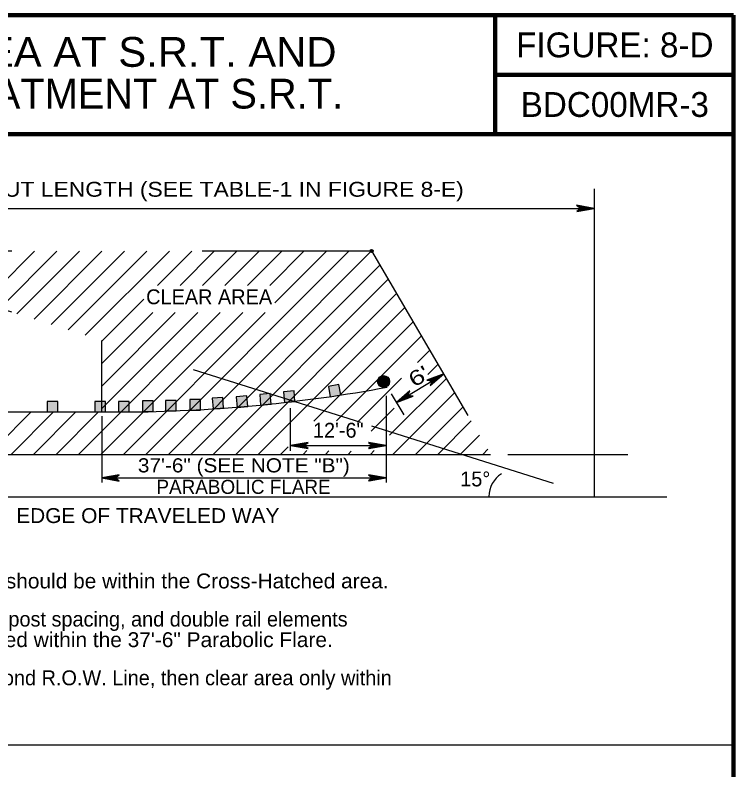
# Model space of a CAD drawing. Extents: x 11.149 to 11.823, y 1.038 to 1.922.
# Drawn here: x 11.4007 to 11.7779, y 1.4804 to 1.8762 of the extents above; entities that cross this region are included whole.
import ezdxf
from ezdxf.enums import TextEntityAlignment as Align

# ---------------------------------------------------------------- set-up
doc = ezdxf.new("R2010")
doc.units = 0
doc.header["$LTSCALE"] = 0.0031
doc.header["$PDMODE"] = 32
doc.header["$PDSIZE"] = 0.00155
doc.linetypes.add('LONG_DASHED', pattern=[7.5, 6, -1.5])
for name, color, linetype, lineweight in [('1', 7, 'Continuous', 90), ('21', 7, 'Continuous', 25), ('24', 7, 'Continuous', 25), ('40', 7, 'Continuous', 25), ('5', 7, 'LONG_DASHED', 25), ('60', 7, 'Continuous', 25)]:
    doc.layers.add(name, color=color, linetype=linetype, lineweight=lineweight)

msp = doc.modelspace()

# ---------------------------------------------------------------- hatches: boundary and pattern name
at = {"layer": '60'}
for points in [[(11.565075, 1.681492), (11.566058, 1.676025), (11.571525, 1.677008), (11.570542, 1.682475)], [(11.541542, 1.678608), (11.542017, 1.673075), (11.54755, 1.673558), (11.547075, 1.679092)], [(11.492433, 1.674642), (11.492433, 1.669092), (11.497983, 1.669092), (11.497983, 1.674642)], [(11.504067, 1.67525), (11.504542, 1.669708), (11.510083, 1.670192), (11.5096, 1.675725)], [(11.51675, 1.676042), (11.517233, 1.670508), (11.522767, 1.670992), (11.522292, 1.676525)], [(11.529042, 1.677242), (11.529517, 1.671708), (11.53505, 1.672183), (11.534575, 1.677725)], [(11.417575, 1.673642), (11.417575, 1.668092), (11.423125, 1.668092), (11.423125, 1.673642)], [(11.442575, 1.673642), (11.442575, 1.668092), (11.448125, 1.668092), (11.448125, 1.673642)], [(11.454892, 1.673658), (11.454892, 1.6681), (11.460442, 1.6681), (11.460442, 1.673658)], [(11.467575, 1.673858), (11.467575, 1.6683), (11.473125, 1.6683), (11.473125, 1.673858)], [(11.479658, 1.674158), (11.479658, 1.6686), (11.485217, 1.6686), (11.485217, 1.674158)]]:
    msp.add_hatch(color=256, dxfattribs=at).paths.add_polyline_path(points)

# ---------------------------------------------------------------- linework, layer by layer
at = {"layer": '1'}
for p, q in [((11.194317, 1.876217), (11.77765, 1.876217)), ((11.65265, 1.876217), (11.65265, 1.813717)), ((11.77765, 1.08455), (11.77765, 1.876217)), ((11.65265, 1.844967), (11.77765, 1.844967)), ((11.194317, 1.813717), (11.77765, 1.813717))]:
    msp.add_line(p, q, dxfattribs=at)
at = {"layer": '1', "lineweight": 53}
for p, q in [((11.652833, 1.876217), (11.652833, 1.813692)), ((11.652833, 1.84495), (11.777883, 1.84495))]:
    msp.add_line(p, q, dxfattribs=at)
at = {"layer": '1', "lineweight": 25}
msp.add_line((11.194317, 1.493575), (11.77765, 1.493575), dxfattribs=at)
at = {"layer": '21'}
for radius in [0.003125, 0.002917, 0.002708, 0.0025, 0.002292, 0.002083, 0.001875, 0.001667, 0.001458, 0.00125, 0.001042, 0.000833, 0.000625, 0.000417, 0.000208]:
    msp.add_circle((11.594011, 1.684067), radius, dxfattribs=at)
at = {"layer": '24'}
for p, q in [((11.704592, 1.785133), (11.704592, 1.623642)), ((11.267383, 1.774867), (11.704592, 1.774867)), ((11.600733, 1.673042), (11.62535, 1.687925)), ((11.595308, 1.676492), (11.595308, 1.631025)), ((11.598025, 1.677525), (11.604658, 1.666558)), ((11.242575, 1.668092), (11.462017, 1.668092)), ((11.545242, 1.647775), (11.545242, 1.670025)), ((11.446108, 1.665817), (11.446108, 1.631025)), ((11.545242, 1.6505), (11.595308, 1.6505)), ((11.242575, 1.645867), (11.650125, 1.645867)), ((11.6593, 1.645867), (11.722158, 1.645867)), ((11.446108, 1.633508), (11.595308, 1.633508)), ((11.242642, 1.623642), (11.742692, 1.623642))]:
    msp.add_line(p, q, dxfattribs=at)
at = {"layer": '24', "linetype": 'LONG_DASHED'}
msp.add_line((11.446108, 1.668383), (11.446108, 1.705592), dxfattribs=at)
at = {"layer": '24'}
for points in [[(11.704592, 1.774867), (11.69535, 1.7765), (11.697558, 1.774867), (11.6954, 1.773258), (11.704592, 1.774867), (11.703975, 1.774842), (11.695608, 1.776375), (11.697733, 1.774842), (11.695775, 1.773383), (11.703642, 1.774817), (11.703342, 1.774867), (11.696167, 1.776133), (11.697775, 1.774842), (11.696125, 1.773592), (11.7032, 1.774867), (11.702892, 1.774817), (11.696625, 1.77595), (11.697842, 1.774867), (11.6966, 1.773733), (11.702, 1.774817), (11.701475, 1.774817), (11.697092, 1.775717), (11.697942, 1.774892), (11.697025, 1.773967), (11.701383, 1.774867), (11.700892, 1.774892), (11.697592, 1.775458), (11.698225, 1.774817), (11.697542, 1.774183), (11.700433, 1.774867), (11.699975, 1.774908), (11.697992, 1.775292), (11.698317, 1.774842), (11.697775, 1.77435), (11.699733, 1.774867), (11.698442, 1.775167), (11.698625, 1.774817), (11.698058, 1.774467), (11.699408, 1.774817), (11.698558, 1.775025), (11.698908, 1.77475), (11.698508, 1.774583), (11.698908, 1.774842), (11.6987, 1.774892)], [(11.625575, 1.6881), (11.616817, 1.684717), (11.619558, 1.684458), (11.618542, 1.681967), (11.625575, 1.6881), (11.625058, 1.687767), (11.617108, 1.68475), (11.619717, 1.684533), (11.618792, 1.682267), (11.624792, 1.687575), (11.6245, 1.68745), (11.617708, 1.684833), (11.61975, 1.684558), (11.618983, 1.682633), (11.624383, 1.687383), (11.624142, 1.687183), (11.618192, 1.684908), (11.6198, 1.684608), (11.619317, 1.683), (11.623375, 1.686717), (11.622933, 1.68645), (11.618717, 1.68495), (11.619867, 1.684683), (11.619558, 1.683417), (11.622825, 1.686442), (11.622392, 1.686208), (11.619275, 1.684983), (11.62015, 1.684767), (11.619892, 1.683867), (11.622017, 1.68595), (11.621592, 1.68575), (11.619708, 1.68505), (11.620217, 1.684833), (11.620008, 1.684133), (11.621417, 1.685583), (11.62015, 1.685183), (11.620492, 1.684975), (11.620192, 1.684375), (11.621158, 1.685375), (11.620325, 1.685117), (11.620775, 1.685067), (11.620508, 1.684708), (11.620725, 1.685142), (11.620517, 1.685075)], [(11.600733, 1.673042), (11.609483, 1.676425), (11.60675, 1.676683), (11.607767, 1.679175), (11.600733, 1.673042), (11.60125, 1.673375), (11.6092, 1.6764), (11.606592, 1.676608), (11.607517, 1.678875), (11.601517, 1.673575), (11.601808, 1.673692), (11.6086, 1.676308), (11.606558, 1.676583), (11.607317, 1.678517), (11.601925, 1.673767), (11.602167, 1.673967), (11.608117, 1.676242), (11.606508, 1.676533), (11.606992, 1.678142), (11.602933, 1.674425), (11.603375, 1.674692), (11.607592, 1.6762), (11.606433, 1.676458), (11.60675, 1.677725), (11.603475, 1.6747), (11.603917, 1.674933), (11.607033, 1.676158), (11.606158, 1.676375), (11.606417, 1.677275), (11.604292, 1.675192), (11.604708, 1.675392), (11.6066, 1.676092), (11.606092, 1.676308), (11.6063, 1.677008), (11.604892, 1.675558), (11.606158, 1.675967), (11.605817, 1.676167), (11.606117, 1.676767), (11.60515, 1.675767), (11.605983, 1.676025), (11.605533, 1.676083), (11.6058, 1.676433), (11.605583, 1.676), (11.605792, 1.676075)], [(11.545242, 1.6505), (11.554483, 1.648867), (11.552275, 1.6505), (11.554433, 1.652108), (11.545242, 1.6505), (11.545858, 1.650517), (11.554225, 1.648992), (11.552108, 1.650517), (11.554067, 1.651983), (11.546192, 1.650542), (11.5465, 1.6505), (11.553667, 1.649225), (11.552058, 1.650517), (11.553708, 1.651775), (11.546642, 1.6505), (11.546942, 1.650542), (11.553208, 1.649417), (11.551992, 1.6505), (11.553233, 1.651625), (11.547833, 1.65055), (11.548358, 1.65055), (11.552742, 1.64965), (11.551892, 1.650475), (11.552808, 1.651392), (11.54845, 1.6505), (11.548942, 1.650475), (11.552242, 1.649908), (11.551608, 1.65055), (11.5523, 1.651183), (11.5494, 1.6505), (11.549867, 1.65045), (11.551842, 1.650075), (11.551517, 1.650517), (11.552058, 1.651017), (11.550108, 1.6505), (11.5514, 1.650192), (11.551208, 1.65055), (11.551775, 1.6509), (11.550433, 1.65055), (11.551275, 1.650333), (11.550925, 1.650617), (11.551333, 1.650783), (11.550925, 1.650517), (11.551133, 1.650475)], [(11.595308, 1.6505), (11.586075, 1.652133), (11.588275, 1.6505), (11.586117, 1.648892), (11.595308, 1.6505), (11.5947, 1.650483), (11.586333, 1.652008), (11.58845, 1.650483), (11.586492, 1.649017), (11.594367, 1.650458), (11.594058, 1.6505), (11.586892, 1.651775), (11.5885, 1.650483), (11.586842, 1.649225), (11.593917, 1.6505), (11.593608, 1.650458), (11.587342, 1.651583), (11.588567, 1.6505), (11.587317, 1.649375), (11.592717, 1.65045), (11.5922, 1.65045), (11.587808, 1.65135), (11.588667, 1.650525), (11.587742, 1.649608), (11.592108, 1.6505), (11.591608, 1.650525), (11.588308, 1.651092), (11.58895, 1.65045), (11.588258, 1.649817), (11.591158, 1.6505), (11.590692, 1.65055), (11.588708, 1.650925), (11.589042, 1.650483), (11.5885, 1.649983), (11.59045, 1.6505), (11.589158, 1.650808), (11.589342, 1.65045), (11.588775, 1.6501), (11.590125, 1.65045), (11.589275, 1.650667), (11.589633, 1.650383), (11.589225, 1.650217), (11.589633, 1.650483), (11.589417, 1.650525)], [(11.446108, 1.633508), (11.455342, 1.631875), (11.453133, 1.633508), (11.4553, 1.635108), (11.446108, 1.633508), (11.446717, 1.633525), (11.455083, 1.631992), (11.452967, 1.633525), (11.454925, 1.634983), (11.44705, 1.63355), (11.447358, 1.633508), (11.454525, 1.632233), (11.452917, 1.633525), (11.454567, 1.634775), (11.4475, 1.6335), (11.447808, 1.63355), (11.454067, 1.632417), (11.45285, 1.6335), (11.454092, 1.634633), (11.4487, 1.63355), (11.449217, 1.63355), (11.453608, 1.63265), (11.45275, 1.633475), (11.453675, 1.6344), (11.449308, 1.633508), (11.449808, 1.633475), (11.4531, 1.632908), (11.452467, 1.63355), (11.453158, 1.634183), (11.450258, 1.633508), (11.450725, 1.633458), (11.452708, 1.633075), (11.452375, 1.633525), (11.452917, 1.634017), (11.450967, 1.6335), (11.452258, 1.6332), (11.452067, 1.63355), (11.452633, 1.633908), (11.451292, 1.63355), (11.452142, 1.633342), (11.451783, 1.633617), (11.452192, 1.633783), (11.451783, 1.633525), (11.452, 1.633475)], [(11.595308, 1.633508), (11.586075, 1.635142), (11.588275, 1.633508), (11.586117, 1.6319), (11.595308, 1.633508), (11.5947, 1.633483), (11.586333, 1.635017), (11.58845, 1.633483), (11.586492, 1.632025), (11.594367, 1.633458), (11.594058, 1.633508), (11.586892, 1.634775), (11.5885, 1.633483), (11.586842, 1.632233), (11.593917, 1.633508), (11.593608, 1.633458), (11.587342, 1.634592), (11.588567, 1.633508), (11.587317, 1.632375), (11.592717, 1.633458), (11.5922, 1.633458), (11.587808, 1.634358), (11.588667, 1.633533), (11.587742, 1.632608), (11.592108, 1.633508), (11.591608, 1.633533), (11.588308, 1.6341), (11.58895, 1.633458), (11.588258, 1.632825), (11.591158, 1.633508), (11.590692, 1.63355), (11.588708, 1.633933), (11.589042, 1.633483), (11.5885, 1.632992), (11.59045, 1.633508), (11.589158, 1.633808), (11.589342, 1.633458), (11.588775, 1.633108), (11.590125, 1.633458), (11.589275, 1.633667), (11.589633, 1.633392), (11.589225, 1.633225), (11.589633, 1.633483), (11.589417, 1.633533)]]:
    msp.add_lwpolyline(points, dxfattribs=at)
for centre, radius, start, end in [((11.452878, 2.459014), 0.790977, 270.66208, 280.41598), ((11.662924, 1.623975), 0.013572, 121.18619, 181.05925)]:
    msp.add_arc(centre, radius, start, end, dxfattribs=at)
at = {"layer": '40'}
for p, q in [((11.383733, 1.725283), (11.410842, 1.752392)), ((11.392692, 1.722458), (11.422633, 1.7524)), ((11.40165, 1.719625), (11.434433, 1.752408)), ((11.4106, 1.7168), (11.446225, 1.752417)), ((11.419558, 1.713967), (11.458025, 1.752433)), ((11.428517, 1.711142), (11.469817, 1.752442)), ((11.437475, 1.708317), (11.481617, 1.75245)), ((11.469308, 1.645867), (11.575975, 1.752533)), ((11.47545, 1.7345), (11.493408, 1.752458)), ((11.481092, 1.645867), (11.587775, 1.752542)), ((11.487233, 1.7345), (11.5052, 1.752475)), ((11.499017, 1.7345), (11.517, 1.752483)), ((11.5108, 1.7345), (11.528792, 1.752492)), ((11.522583, 1.7345), (11.540592, 1.7525)), ((11.534375, 1.7345), (11.552383, 1.752517)), ((11.536933, 1.725275), (11.564183, 1.752525)), ((11.492883, 1.645867), (11.592133, 1.745117)), ((11.504667, 1.645867), (11.596492, 1.737692)), ((11.51645, 1.645867), (11.60085, 1.730267)), ((11.4461, 1.705158), (11.468233, 1.727283)), ((11.528233, 1.645867), (11.605208, 1.722842)), ((11.43395, 1.645867), (11.508308, 1.720225)), ((11.445742, 1.645867), (11.5201, 1.720225)), ((11.446, 1.6697), (11.496533, 1.720225)), ((11.446067, 1.693333), (11.472958, 1.720225)), ((11.446108, 1.681592), (11.484742, 1.720225)), ((11.457525, 1.645867), (11.531883, 1.720225)), ((11.557375, 1.663217), (11.609567, 1.715417)), ((11.569358, 1.663433), (11.613925, 1.707983)), ((11.611842, 1.694117), (11.618283, 1.700558)), ((11.61725, 1.687742), (11.622642, 1.693133)), ((11.580392, 1.662675), (11.603525, 1.685808)), ((11.597158, 1.655867), (11.627, 1.685708)), ((11.59895, 1.645867), (11.631358, 1.678283)), ((11.610725, 1.645867), (11.635717, 1.670858)), ((11.386817, 1.645867), (11.409033, 1.668092)), ((11.3986, 1.645867), (11.420825, 1.668092)), ((11.410383, 1.645867), (11.432608, 1.668092)), ((11.422167, 1.645867), (11.4444, 1.668092)), ((11.587583, 1.658075), (11.599608, 1.6701)), ((11.622517, 1.645867), (11.640083, 1.663433)), ((11.6343, 1.645867), (11.644442, 1.656008)), ((11.540017, 1.645867), (11.544025, 1.649867)), ((11.551808, 1.645867), (11.55375, 1.647817)), ((11.563592, 1.645867), (11.565358, 1.647633)), ((11.575375, 1.645867), (11.577075, 1.647558)), ((11.587158, 1.645867), (11.589158, 1.647867)), ((11.646083, 1.645867), (11.6488, 1.648575))]:
    msp.add_line(p, q, dxfattribs=at)
msp.add_point((11.587775, 1.752542), dxfattribs=at)
at = {"layer": '5'}
for p, q in [((11.298883, 1.752542), (11.587775, 1.752542)), ((11.30345, 1.750633), (11.581983, 1.662692)), ((11.587775, 1.752542), (11.662925, 1.623975)), ((11.58765, 1.6609), (11.704592, 1.623975))]:
    msp.add_line(p, q, dxfattribs=at)
at = {"layer": '60'}
for points in [[(11.565075, 1.681492), (11.566058, 1.676025), (11.571525, 1.677008), (11.570542, 1.682475)], [(11.541542, 1.678608), (11.542017, 1.673075), (11.54755, 1.673558), (11.547075, 1.679092)], [(11.492433, 1.674642), (11.492433, 1.669092), (11.497983, 1.669092), (11.497983, 1.674642)], [(11.504067, 1.67525), (11.504542, 1.669708), (11.510083, 1.670192), (11.5096, 1.675725)], [(11.51675, 1.676042), (11.517233, 1.670508), (11.522767, 1.670992), (11.522292, 1.676525)], [(11.529042, 1.677242), (11.529517, 1.671708), (11.53505, 1.672183), (11.534575, 1.677725)], [(11.417575, 1.673642), (11.417575, 1.668092), (11.423125, 1.668092), (11.423125, 1.673642)], [(11.442575, 1.673642), (11.442575, 1.668092), (11.448125, 1.668092), (11.448125, 1.673642)], [(11.454892, 1.673658), (11.454892, 1.6681), (11.460442, 1.6681), (11.460442, 1.673658)], [(11.467575, 1.673858), (11.467575, 1.6683), (11.473125, 1.6683), (11.473125, 1.673858)], [(11.479658, 1.674158), (11.479658, 1.6686), (11.485217, 1.6686), (11.485217, 1.674158)]]:
    msp.add_lwpolyline(points, close=True, dxfattribs=at)

# ---------------------------------------------------------------- texts
at = {"layer": '1'}
for s, height, width, p in [('CLEAR AREA AT S.R.T. AND', 0.01562, 1.05, (11.422521, 1.8491)), ('L  = RUNOUT LENGTH (SEE TABLE-1 IN FIGURE 8-E)', 0.0078, 1.15, (11.485983, 1.780967)), ('37\'-6" (SEE NOTE "B")', 0.00741, 1.1, (11.520708, 1.6364)), ('EDGE OF TRAVELED WAY', 0.0078, 1.05, (11.470321, 1.60985))]:
    msp.add_text(s, height=height, dxfattribs=dict(at, width=width)).set_placement(p, align=Align.CENTER)
for s, height, p in [('FIGURE: 8-D', 0.01303, (11.715383, 1.854075)), ('SLOPE TREATMENT AT S.R.T.', 0.01562, (11.422529, 1.827225)), ('BDC00MR-3', 0.01303, (11.715379, 1.822825)), ('CLEAR AREA', 0.0078, (11.502479, 1.724583)), ('12\'-6"', 0.0078, (11.570271, 1.6546)), ('15°', 0.0078, (11.642138, 1.629067)), ('PARABOLIC FLARE', 0.00741, (11.520542, 1.625117))]:
    msp.add_text(s, height=height, dxfattribs=at).set_placement(p, align=Align.CENTER)
at = {"layer": '1', "width": 1.35}
msp.add_text("6'", height=0.0078, rotation=31.159, dxfattribs=at).set_placement((11.614586, 1.68351), align=Align.CENTER)
at = {"layer": '1', "width": 1.05}
for s, p in [('No fixed objects should be within the Cross-Hatched area.', (11.314833, 1.575575)), ('should not be used within the 37\'-6" Parabolic Flare.', (11.314833, 1.544775))]:
    msp.add_text(s, height=0.0078, dxfattribs=at).set_placement(p)
at = {"layer": '1'}
for s, p in [('Rub rail, reduced post spacing, and double rail elements', (11.314833, 1.555575)), ('If L   extends beyond R.O.W. Line, then clear area only within', (11.314833, 1.524775))]:
    msp.add_text(s, height=0.0078, dxfattribs=at).set_placement(p)

doc.saveas('drawing.dxf')
